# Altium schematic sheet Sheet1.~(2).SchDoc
size A3; SheetNumber: 1; SheetTotal: 1
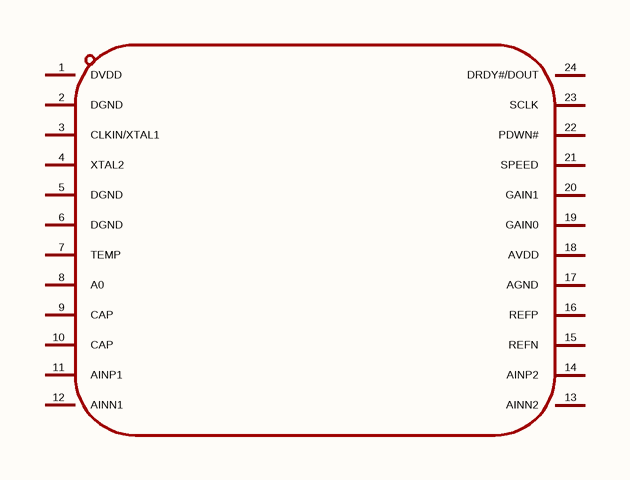
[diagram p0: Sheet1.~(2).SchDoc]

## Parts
U??  ads1232ipwr  [TSSOP-24_L7.8-W4.4-P0.65-LS6.4-BL]  (value not drawn)

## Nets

Not connected (* = marked no-connect by the designer): U?? 1(DVDD) 2(DGND) 3(CLKIN/XTAL1) 4(XTAL2) 5(DGND) 6(DGND) 7(TEMP) 8(A0) 9(CAP) 10(CAP) 11(AINP1) 12(AINN1) 13(AINN2) 14(AINP2) 15(REFN) 16(REFP) 17(AGND) 18(AVDD) 19(GAIN0) 20(GAIN1) 21(SPEED) 22(PDWN#) 23(SCLK) 24(DRDY#/DOUT)

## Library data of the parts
U?? = ads1232ipwr: 分辨率(位):24;采样率:10Hz;工作电压:2.7V~5.3V;接口类型:SPI;; Manufacturer: TI(德州仪器); AddInBom: yes; ModelId: 57e278220af748a2882c4abba4094eb9; ModelName: TSSOP-24_L7.8-W4.4-H1.0-LS6.4-P0.65; ModelTransform: 252.188,307.086,0,90,0,0,0,0,0; Resolution (Bits): 24; Sampling Rate: 10Hz; number of channels: 2; Interface: SPI; differential input: 是; Clock/Oscillator: 内置；外置; Clock Frequency: 4.9152MHz；200kHz~8MHz; Voltage Reference: 外置; Programmable Gain: 支持; Temperature Sensors: 内置; ADC architecture: Sigma-Delta; Data rate: 80Hz；10Hz; Quiescent Current (Iq): 1.3uA; Full-Scale Range(FSR): 39mV；1.25V；19.5mV；2.5V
